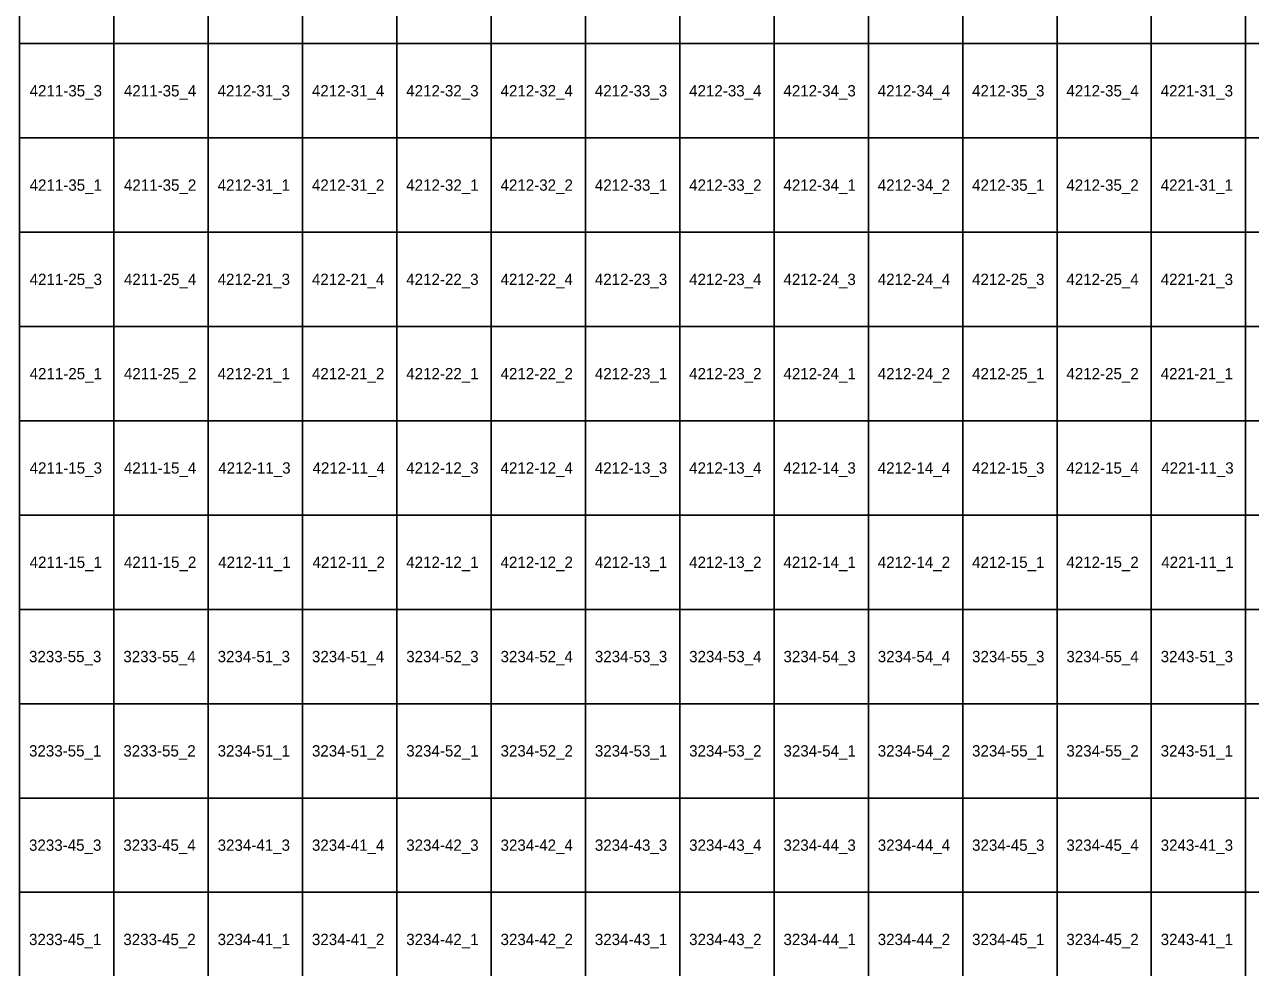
# Model space of a CAD drawing. Extents: x 312500 to 765000, y 172500 to 440000.
# Drawn here: x 420129 to 452629, y 290507 to 315507 of the extents above; entities that cross this region are included whole.
import ezdxf

# ---------------------------------------------------------------- set-up
doc = ezdxf.new("R2010")
doc.units = 0
doc.layers.add('Topo5_ramis_TKS2025', color=7, linetype='Continuous')
doc.layers.add('Topo5_ramis_TKS2025_Nr', color=7, linetype='Continuous')

msp = doc.modelspace()

# ---------------------------------------------------------------- linework, layer by layer
at = {"layer": 'Topo5_ramis_TKS2025'}
for points in [[(420000, 315000), (420000, 317500), (422500, 317500), (422500, 315000), (420000, 315000)], [(422500, 315000), (422500, 317500), (425000, 317500), (425000, 315000), (422500, 315000)], [(425000, 315000), (425000, 317500), (427500, 317500), (427500, 315000), (425000, 315000)], [(427500, 315000), (427500, 317500), (430000, 317500), (430000, 315000), (427500, 315000)], [(430000, 315000), (430000, 317500), (432500, 317500), (432500, 315000), (430000, 315000)], [(432500, 315000), (432500, 317500), (435000, 317500), (435000, 315000), (432500, 315000)], [(435000, 315000), (435000, 317500), (437500, 317500), (437500, 315000), (435000, 315000)], [(437500, 315000), (437500, 317500), (440000, 317500), (440000, 315000), (437500, 315000)], [(440000, 315000), (440000, 317500), (442500, 317500), (442500, 315000), (440000, 315000)], [(442500, 315000), (442500, 317500), (445000, 317500), (445000, 315000), (442500, 315000)], [(445000, 315000), (445000, 317500), (447500, 317500), (447500, 315000), (445000, 315000)], [(447500, 315000), (447500, 317500), (450000, 317500), (450000, 315000), (447500, 315000)], [(450000, 315000), (450000, 317500), (452500, 317500), (452500, 315000), (450000, 315000)], [(452500, 315000), (452500, 317500), (455000, 317500), (455000, 315000), (452500, 315000)], [(420000, 312500), (420000, 315000), (422500, 315000), (422500, 312500), (420000, 312500)], [(422500, 312500), (422500, 315000), (425000, 315000), (425000, 312500), (422500, 312500)], [(425000, 312500), (425000, 315000), (427500, 315000), (427500, 312500), (425000, 312500)], [(427500, 312500), (427500, 315000), (430000, 315000), (430000, 312500), (427500, 312500)], [(430000, 312500), (430000, 315000), (432500, 315000), (432500, 312500), (430000, 312500)], [(432500, 312500), (432500, 315000), (435000, 315000), (435000, 312500), (432500, 312500)], [(435000, 312500), (435000, 315000), (437500, 315000), (437500, 312500), (435000, 312500)], [(437500, 312500), (437500, 315000), (440000, 315000), (440000, 312500), (437500, 312500)], [(440000, 312500), (440000, 315000), (442500, 315000), (442500, 312500), (440000, 312500)], [(442500, 312500), (442500, 315000), (445000, 315000), (445000, 312500), (442500, 312500)], [(445000, 312500), (445000, 315000), (447500, 315000), (447500, 312500), (445000, 312500)], [(447500, 312500), (447500, 315000), (450000, 315000), (450000, 312500), (447500, 312500)], [(450000, 312500), (450000, 315000), (452500, 315000), (452500, 312500), (450000, 312500)], [(452500, 312500), (452500, 315000), (455000, 315000), (455000, 312500), (452500, 312500)], [(420000, 310000), (420000, 312500), (422500, 312500), (422500, 310000), (420000, 310000)], [(422500, 310000), (422500, 312500), (425000, 312500), (425000, 310000), (422500, 310000)], [(425000, 310000), (425000, 312500), (427500, 312500), (427500, 310000), (425000, 310000)], [(427500, 310000), (427500, 312500), (430000, 312500), (430000, 310000), (427500, 310000)], [(430000, 310000), (430000, 312500), (432500, 312500), (432500, 310000), (430000, 310000)], [(432500, 310000), (432500, 312500), (435000, 312500), (435000, 310000), (432500, 310000)], [(435000, 310000), (435000, 312500), (437500, 312500), (437500, 310000), (435000, 310000)], [(437500, 310000), (437500, 312500), (440000, 312500), (440000, 310000), (437500, 310000)], [(440000, 310000), (440000, 312500), (442500, 312500), (442500, 310000), (440000, 310000)], [(442500, 310000), (442500, 312500), (445000, 312500), (445000, 310000), (442500, 310000)], [(445000, 310000), (445000, 312500), (447500, 312500), (447500, 310000), (445000, 310000)], [(447500, 310000), (447500, 312500), (450000, 312500), (450000, 310000), (447500, 310000)], [(450000, 310000), (450000, 312500), (452500, 312500), (452500, 310000), (450000, 310000)], [(452500, 310000), (452500, 312500), (455000, 312500), (455000, 310000), (452500, 310000)], [(420000, 307500), (420000, 310000), (422500, 310000), (422500, 307500), (420000, 307500)], [(422500, 307500), (422500, 310000), (425000, 310000), (425000, 307500), (422500, 307500)], [(425000, 307500), (425000, 310000), (427500, 310000), (427500, 307500), (425000, 307500)], [(427500, 307500), (427500, 310000), (430000, 310000), (430000, 307500), (427500, 307500)], [(430000, 307500), (430000, 310000), (432500, 310000), (432500, 307500), (430000, 307500)], [(432500, 307500), (432500, 310000), (435000, 310000), (435000, 307500), (432500, 307500)], [(435000, 307500), (435000, 310000), (437500, 310000), (437500, 307500), (435000, 307500)], [(437500, 307500), (437500, 310000), (440000, 310000), (440000, 307500), (437500, 307500)], [(440000, 307500), (440000, 310000), (442500, 310000), (442500, 307500), (440000, 307500)], [(442500, 307500), (442500, 310000), (445000, 310000), (445000, 307500), (442500, 307500)], [(445000, 307500), (445000, 310000), (447500, 310000), (447500, 307500), (445000, 307500)], [(447500, 307500), (447500, 310000), (450000, 310000), (450000, 307500), (447500, 307500)], [(450000, 307500), (450000, 310000), (452500, 310000), (452500, 307500), (450000, 307500)], [(452500, 307500), (452500, 310000), (455000, 310000), (455000, 307500), (452500, 307500)], [(420000, 305000), (420000, 307500), (422500, 307500), (422500, 305000), (420000, 305000)], [(422500, 305000), (422500, 307500), (425000, 307500), (425000, 305000), (422500, 305000)], [(425000, 305000), (425000, 307500), (427500, 307500), (427500, 305000), (425000, 305000)], [(427500, 305000), (427500, 307500), (430000, 307500), (430000, 305000), (427500, 305000)], [(430000, 305000), (430000, 307500), (432500, 307500), (432500, 305000), (430000, 305000)], [(432500, 305000), (432500, 307500), (435000, 307500), (435000, 305000), (432500, 305000)], [(435000, 305000), (435000, 307500), (437500, 307500), (437500, 305000), (435000, 305000)], [(437500, 305000), (437500, 307500), (440000, 307500), (440000, 305000), (437500, 305000)], [(440000, 305000), (440000, 307500), (442500, 307500), (442500, 305000), (440000, 305000)], [(442500, 305000), (442500, 307500), (445000, 307500), (445000, 305000), (442500, 305000)], [(445000, 305000), (445000, 307500), (447500, 307500), (447500, 305000), (445000, 305000)], [(447500, 305000), (447500, 307500), (450000, 307500), (450000, 305000), (447500, 305000)], [(450000, 305000), (450000, 307500), (452500, 307500), (452500, 305000), (450000, 305000)], [(452500, 305000), (452500, 307500), (455000, 307500), (455000, 305000), (452500, 305000)], [(420000, 302500), (420000, 305000), (422500, 305000), (422500, 302500), (420000, 302500)], [(422500, 302500), (422500, 305000), (425000, 305000), (425000, 302500), (422500, 302500)], [(425000, 302500), (425000, 305000), (427500, 305000), (427500, 302500), (425000, 302500)], [(427500, 302500), (427500, 305000), (430000, 305000), (430000, 302500), (427500, 302500)], [(430000, 302500), (430000, 305000), (432500, 305000), (432500, 302500), (430000, 302500)], [(432500, 302500), (432500, 305000), (435000, 305000), (435000, 302500), (432500, 302500)], [(435000, 302500), (435000, 305000), (437500, 305000), (437500, 302500), (435000, 302500)], [(437500, 302500), (437500, 305000), (440000, 305000), (440000, 302500), (437500, 302500)], [(440000, 302500), (440000, 305000), (442500, 305000), (442500, 302500), (440000, 302500)], [(442500, 302500), (442500, 305000), (445000, 305000), (445000, 302500), (442500, 302500)], [(445000, 302500), (445000, 305000), (447500, 305000), (447500, 302500), (445000, 302500)], [(447500, 302500), (447500, 305000), (450000, 305000), (450000, 302500), (447500, 302500)], [(450000, 302500), (450000, 305000), (452500, 305000), (452500, 302500), (450000, 302500)], [(452500, 302500), (452500, 305000), (455000, 305000), (455000, 302500), (452500, 302500)], [(420000, 300000), (420000, 302500), (422500, 302500), (422500, 300000), (420000, 300000)], [(422500, 300000), (422500, 302500), (425000, 302500), (425000, 300000), (422500, 300000)], [(425000, 300000), (425000, 302500), (427500, 302500), (427500, 300000), (425000, 300000)], [(427500, 300000), (427500, 302500), (430000, 302500), (430000, 300000), (427500, 300000)], [(430000, 300000), (430000, 302500), (432500, 302500), (432500, 300000), (430000, 300000)], [(432500, 300000), (432500, 302500), (435000, 302500), (435000, 300000), (432500, 300000)], [(435000, 300000), (435000, 302500), (437500, 302500), (437500, 300000), (435000, 300000)], [(437500, 300000), (437500, 302500), (440000, 302500), (440000, 300000), (437500, 300000)], [(440000, 300000), (440000, 302500), (442500, 302500), (442500, 300000), (440000, 300000)], [(442500, 300000), (442500, 302500), (445000, 302500), (445000, 300000), (442500, 300000)], [(445000, 300000), (445000, 302500), (447500, 302500), (447500, 300000), (445000, 300000)], [(447500, 300000), (447500, 302500), (450000, 302500), (450000, 300000), (447500, 300000)], [(450000, 300000), (450000, 302500), (452500, 302500), (452500, 300000), (450000, 300000)], [(452500, 300000), (452500, 302500), (455000, 302500), (455000, 300000), (452500, 300000)], [(420000, 297500), (420000, 300000), (422500, 300000), (422500, 297500), (420000, 297500)], [(422500, 297500), (422500, 300000), (425000, 300000), (425000, 297500), (422500, 297500)], [(425000, 297500), (425000, 300000), (427500, 300000), (427500, 297500), (425000, 297500)], [(427500, 297500), (427500, 300000), (430000, 300000), (430000, 297500), (427500, 297500)], [(430000, 297500), (430000, 300000), (432500, 300000), (432500, 297500), (430000, 297500)], [(432500, 297500), (432500, 300000), (435000, 300000), (435000, 297500), (432500, 297500)], [(435000, 297500), (435000, 300000), (437500, 300000), (437500, 297500), (435000, 297500)], [(437500, 297500), (437500, 300000), (440000, 300000), (440000, 297500), (437500, 297500)], [(440000, 297500), (440000, 300000), (442500, 300000), (442500, 297500), (440000, 297500)], [(442500, 297500), (442500, 300000), (445000, 300000), (445000, 297500), (442500, 297500)], [(445000, 297500), (445000, 300000), (447500, 300000), (447500, 297500), (445000, 297500)], [(447500, 297500), (447500, 300000), (450000, 300000), (450000, 297500), (447500, 297500)], [(450000, 297500), (450000, 300000), (452500, 300000), (452500, 297500), (450000, 297500)], [(452500, 297500), (452500, 300000), (455000, 300000), (455000, 297500), (452500, 297500)], [(420000, 295000), (420000, 297500), (422500, 297500), (422500, 295000), (420000, 295000)], [(422500, 295000), (422500, 297500), (425000, 297500), (425000, 295000), (422500, 295000)], [(425000, 295000), (425000, 297500), (427500, 297500), (427500, 295000), (425000, 295000)], [(427500, 295000), (427500, 297500), (430000, 297500), (430000, 295000), (427500, 295000)], [(430000, 295000), (430000, 297500), (432500, 297500), (432500, 295000), (430000, 295000)], [(432500, 295000), (432500, 297500), (435000, 297500), (435000, 295000), (432500, 295000)], [(435000, 295000), (435000, 297500), (437500, 297500), (437500, 295000), (435000, 295000)], [(437500, 295000), (437500, 297500), (440000, 297500), (440000, 295000), (437500, 295000)], [(440000, 295000), (440000, 297500), (442500, 297500), (442500, 295000), (440000, 295000)], [(442500, 295000), (442500, 297500), (445000, 297500), (445000, 295000), (442500, 295000)], [(445000, 295000), (445000, 297500), (447500, 297500), (447500, 295000), (445000, 295000)], [(447500, 295000), (447500, 297500), (450000, 297500), (450000, 295000), (447500, 295000)], [(450000, 295000), (450000, 297500), (452500, 297500), (452500, 295000), (450000, 295000)], [(452500, 295000), (452500, 297500), (455000, 297500), (455000, 295000), (452500, 295000)], [(420000, 292500), (420000, 295000), (422500, 295000), (422500, 292500), (420000, 292500)], [(422500, 292500), (422500, 295000), (425000, 295000), (425000, 292500), (422500, 292500)], [(425000, 292500), (425000, 295000), (427500, 295000), (427500, 292500), (425000, 292500)], [(427500, 292500), (427500, 295000), (430000, 295000), (430000, 292500), (427500, 292500)], [(430000, 292500), (430000, 295000), (432500, 295000), (432500, 292500), (430000, 292500)], [(432500, 292500), (432500, 295000), (435000, 295000), (435000, 292500), (432500, 292500)], [(435000, 292500), (435000, 295000), (437500, 295000), (437500, 292500), (435000, 292500)], [(437500, 292500), (437500, 295000), (440000, 295000), (440000, 292500), (437500, 292500)], [(440000, 292500), (440000, 295000), (442500, 295000), (442500, 292500), (440000, 292500)], [(442500, 292500), (442500, 295000), (445000, 295000), (445000, 292500), (442500, 292500)], [(445000, 292500), (445000, 295000), (447500, 295000), (447500, 292500), (445000, 292500)], [(447500, 292500), (447500, 295000), (450000, 295000), (450000, 292500), (447500, 292500)], [(450000, 292500), (450000, 295000), (452500, 295000), (452500, 292500), (450000, 292500)], [(452500, 292500), (452500, 295000), (455000, 295000), (455000, 292500), (452500, 292500)], [(420000, 290000), (420000, 292500), (422500, 292500), (422500, 290000), (420000, 290000)], [(422500, 290000), (422500, 292500), (425000, 292500), (425000, 290000), (422500, 290000)], [(425000, 290000), (425000, 292500), (427500, 292500), (427500, 290000), (425000, 290000)], [(427500, 290000), (427500, 292500), (430000, 292500), (430000, 290000), (427500, 290000)], [(430000, 290000), (430000, 292500), (432500, 292500), (432500, 290000), (430000, 290000)], [(432500, 290000), (432500, 292500), (435000, 292500), (435000, 290000), (432500, 290000)], [(435000, 290000), (435000, 292500), (437500, 292500), (437500, 290000), (435000, 290000)], [(437500, 290000), (437500, 292500), (440000, 292500), (440000, 290000), (437500, 290000)], [(440000, 290000), (440000, 292500), (442500, 292500), (442500, 290000), (440000, 290000)], [(442500, 290000), (442500, 292500), (445000, 292500), (445000, 290000), (442500, 290000)], [(445000, 290000), (445000, 292500), (447500, 292500), (447500, 290000), (445000, 290000)], [(447500, 290000), (447500, 292500), (450000, 292500), (450000, 290000), (447500, 290000)], [(450000, 290000), (450000, 292500), (452500, 292500), (452500, 290000), (450000, 290000)], [(452500, 290000), (452500, 292500), (455000, 292500), (455000, 290000), (452500, 290000)]]:
    msp.add_lwpolyline(points, dxfattribs=at)

# ---------------------------------------------------------------- texts
at = {"layer": 'Topo5_ramis_TKS2025_Nr'}
for s, p in [('4211-35_3', (420264, 313600)), ('4211-35_4', (422764, 313600)), ('4212-31_3', (425248, 313600)), ('4212-31_4', (427748, 313600)), ('4212-32_3', (430248, 313600)), ('4212-32_4', (432748, 313600)), ('4212-33_3', (435248, 313600)), ('4212-33_4', (437748, 313600)), ('4212-34_3', (440248, 313600)), ('4212-34_4', (442748, 313600)), ('4212-35_3', (445248, 313600)), ('4212-35_4', (447748, 313600)), ('4221-31_3', (450248, 313600)), ('4211-35_1', (420264, 311100)), ('4211-35_2', (422764, 311100)), ('4212-31_1', (425248, 311100)), ('4212-31_2', (427748, 311100)), ('4212-32_1', (430248, 311100)), ('4212-32_2', (432748, 311100)), ('4212-33_1', (435248, 311100)), ('4212-33_2', (437748, 311100)), ('4212-34_1', (440248, 311100)), ('4212-34_2', (442748, 311100)), ('4212-35_1', (445248, 311100)), ('4212-35_2', (447748, 311100)), ('4221-31_1', (450248, 311100)), ('4211-25_3', (420264, 308600)), ('4211-25_4', (422764, 308600)), ('4212-21_3', (425248, 308600)), ('4212-21_4', (427748, 308600)), ('4212-22_3', (430248, 308600)), ('4212-22_4', (432748, 308600)), ('4212-23_3', (435248, 308600)), ('4212-23_4', (437748, 308600)), ('4212-24_3', (440248, 308600)), ('4212-24_4', (442748, 308600)), ('4212-25_3', (445248, 308600)), ('4212-25_4', (447748, 308600)), ('4221-21_3', (450248, 308600)), ('4211-25_1', (420264, 306100)), ('4211-25_2', (422764, 306100)), ('4212-21_1', (425248, 306100)), ('4212-21_2', (427748, 306100)), ('4212-22_1', (430248, 306100)), ('4212-22_2', (432748, 306100)), ('4212-23_1', (435248, 306100)), ('4212-23_2', (437748, 306100)), ('4212-24_1', (440248, 306100)), ('4212-24_2', (442748, 306100)), ('4212-25_1', (445248, 306100)), ('4212-25_2', (447748, 306100)), ('4221-21_1', (450248, 306100)), ('4211-15_3', (420264, 303600)), ('4211-15_4', (422764, 303600)), ('4212-11_3', (425264, 303600)), ('4212-11_4', (427764, 303600)), ('4212-12_3', (430248, 303600)), ('4212-12_4', (432748, 303600)), ('4212-13_3', (435248, 303600)), ('4212-13_4', (437748, 303600)), ('4212-14_3', (440248, 303600)), ('4212-14_4', (442748, 303600)), ('4212-15_3', (445248, 303600)), ('4212-15_4', (447748, 303600)), ('4221-11_3', (450264, 303600)), ('4211-15_1', (420264, 301100)), ('4211-15_2', (422764, 301100)), ('4212-11_1', (425264, 301100)), ('4212-11_2', (427764, 301100)), ('4212-12_1', (430248, 301100)), ('4212-12_2', (432748, 301100)), ('4212-13_1', (435248, 301100)), ('4212-13_2', (437748, 301100)), ('4212-14_1', (440248, 301100)), ('4212-14_2', (442748, 301100)), ('4212-15_1', (445248, 301100)), ('4212-15_2', (447748, 301100)), ('4221-11_1', (450264, 301100)), ('3233-55_3', (420248, 298600)), ('3233-55_4', (422748, 298600)), ('3234-51_3', (425248, 298600)), ('3234-51_4', (427748, 298600)), ('3234-52_3', (430248, 298600)), ('3234-52_4', (432748, 298600)), ('3234-53_3', (435248, 298600)), ('3234-53_4', (437748, 298600)), ('3234-54_3', (440248, 298600)), ('3234-54_4', (442748, 298600)), ('3234-55_3', (445248, 298600)), ('3234-55_4', (447748, 298600)), ('3243-51_3', (450248, 298600)), ('3233-55_1', (420248, 296100)), ('3233-55_2', (422748, 296100)), ('3234-51_1', (425248, 296100)), ('3234-51_2', (427748, 296100)), ('3234-52_1', (430248, 296100)), ('3234-52_2', (432748, 296100)), ('3234-53_1', (435248, 296100)), ('3234-53_2', (437748, 296100)), ('3234-54_1', (440248, 296100)), ('3234-54_2', (442748, 296100)), ('3234-55_1', (445248, 296100)), ('3234-55_2', (447748, 296100)), ('3243-51_1', (450248, 296100)), ('3233-45_3', (420248, 293600)), ('3233-45_4', (422748, 293600)), ('3234-41_3', (425248, 293600)), ('3234-41_4', (427748, 293600)), ('3234-42_3', (430248, 293600)), ('3234-42_4', (432748, 293600)), ('3234-43_3', (435248, 293600)), ('3234-43_4', (437748, 293600)), ('3234-44_3', (440248, 293600)), ('3234-44_4', (442748, 293600)), ('3234-45_3', (445248, 293600)), ('3234-45_4', (447748, 293600)), ('3243-41_3', (450248, 293600)), ('3233-45_1', (420248, 291100)), ('3233-45_2', (422748, 291100)), ('3234-41_1', (425248, 291100)), ('3234-41_2', (427748, 291100)), ('3234-42_1', (430248, 291100)), ('3234-42_2', (432748, 291100)), ('3234-43_1', (435248, 291100)), ('3234-43_2', (437748, 291100)), ('3234-44_1', (440248, 291100)), ('3234-44_2', (442748, 291100)), ('3234-45_1', (445248, 291100)), ('3234-45_2', (447748, 291100)), ('3243-41_1', (450248, 291100))]:
    msp.add_text(s, height=300, dxfattribs=at).set_placement(p)

doc.saveas('drawing.dxf')
